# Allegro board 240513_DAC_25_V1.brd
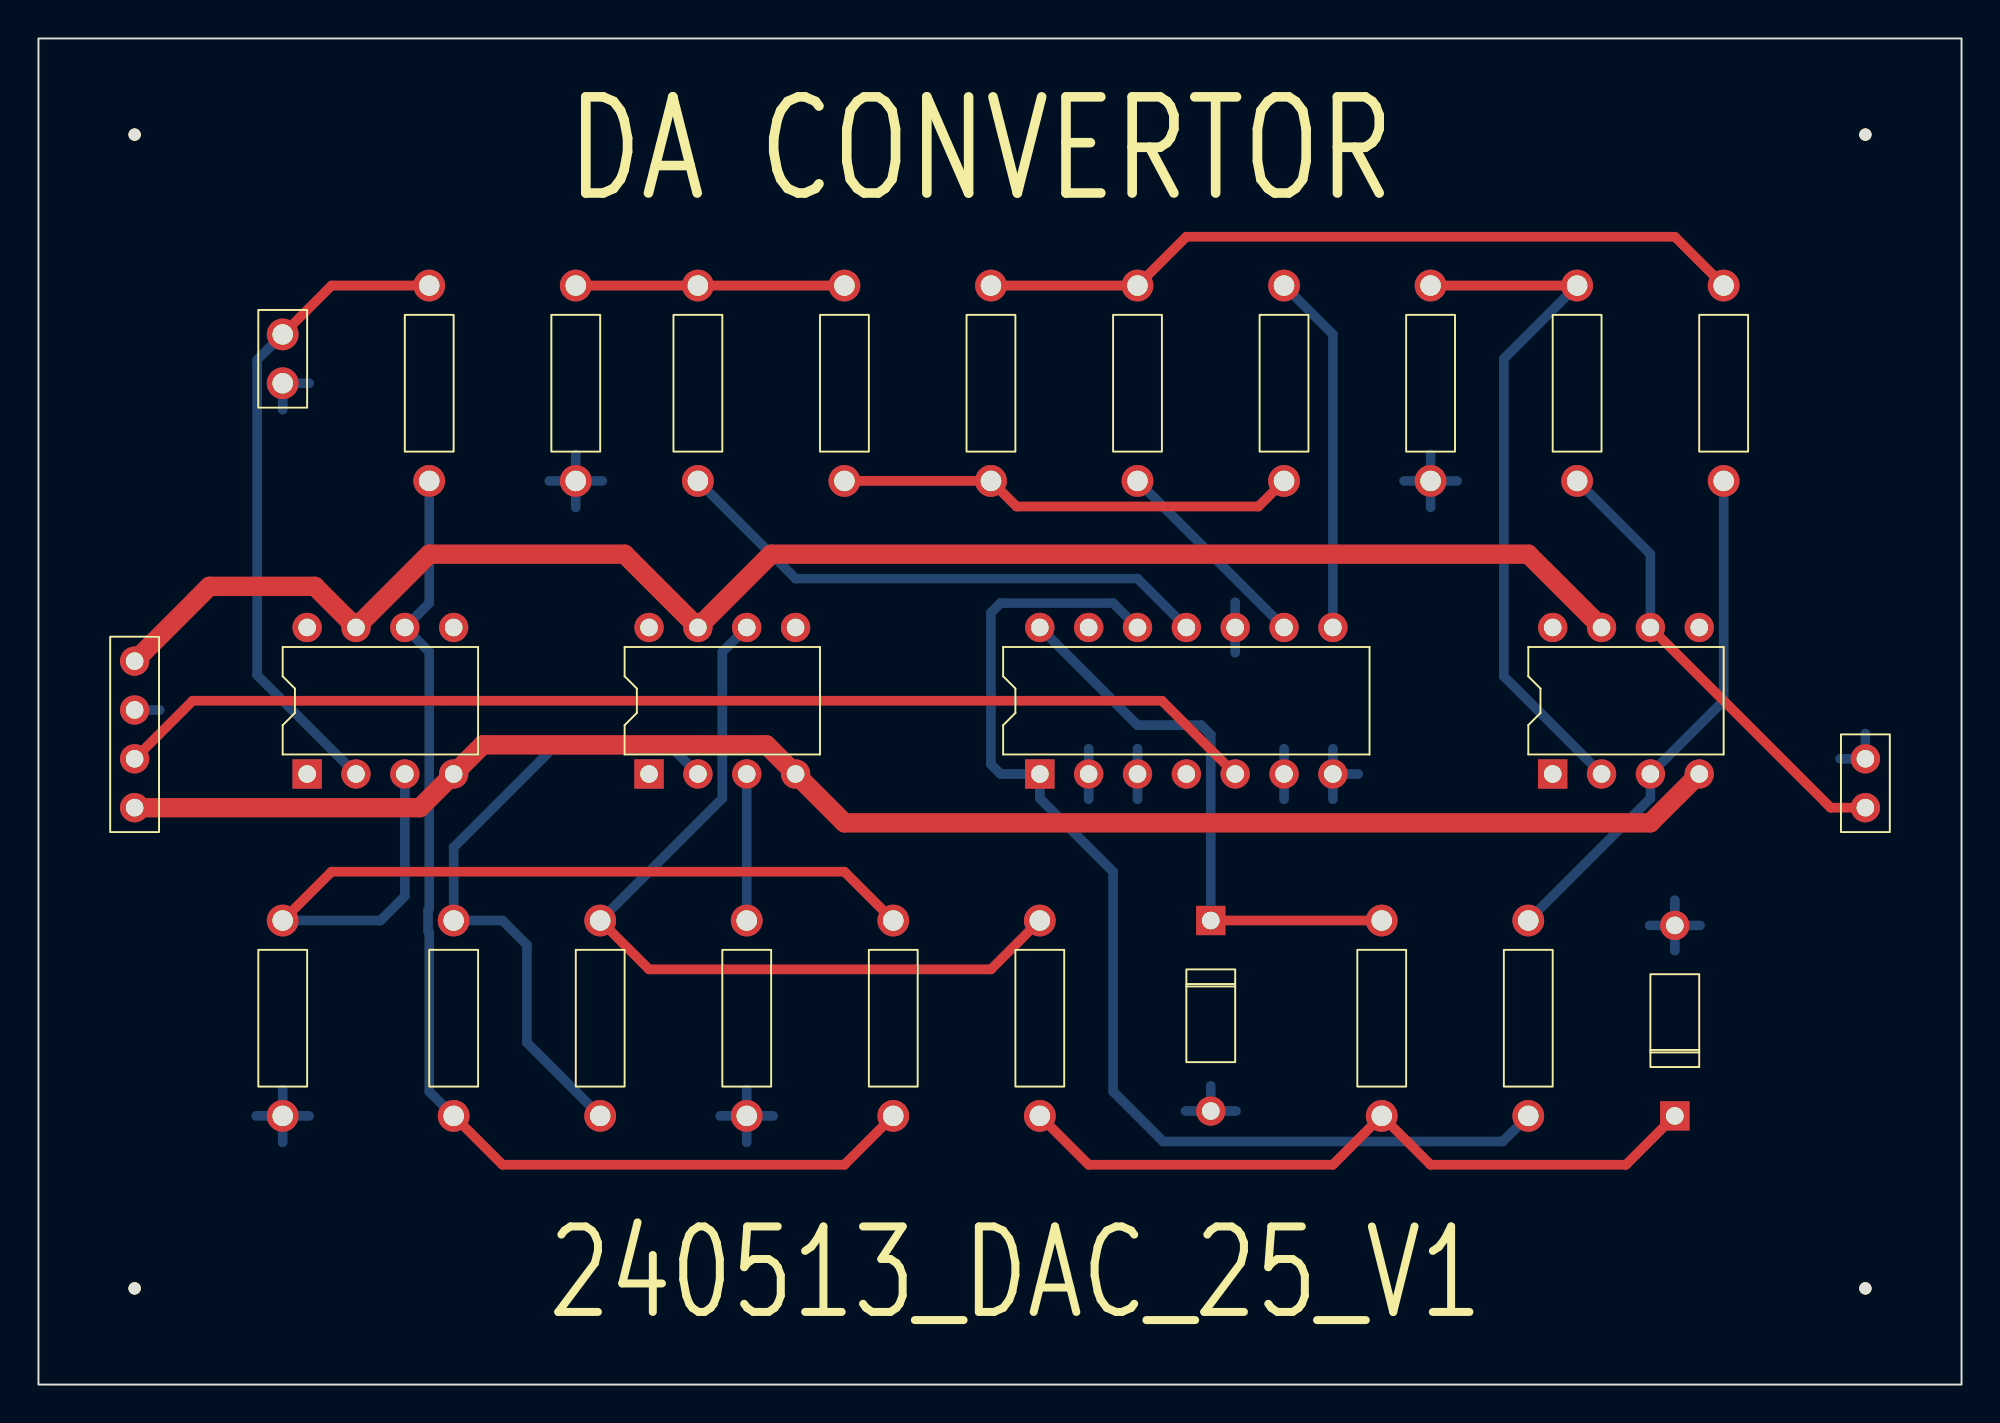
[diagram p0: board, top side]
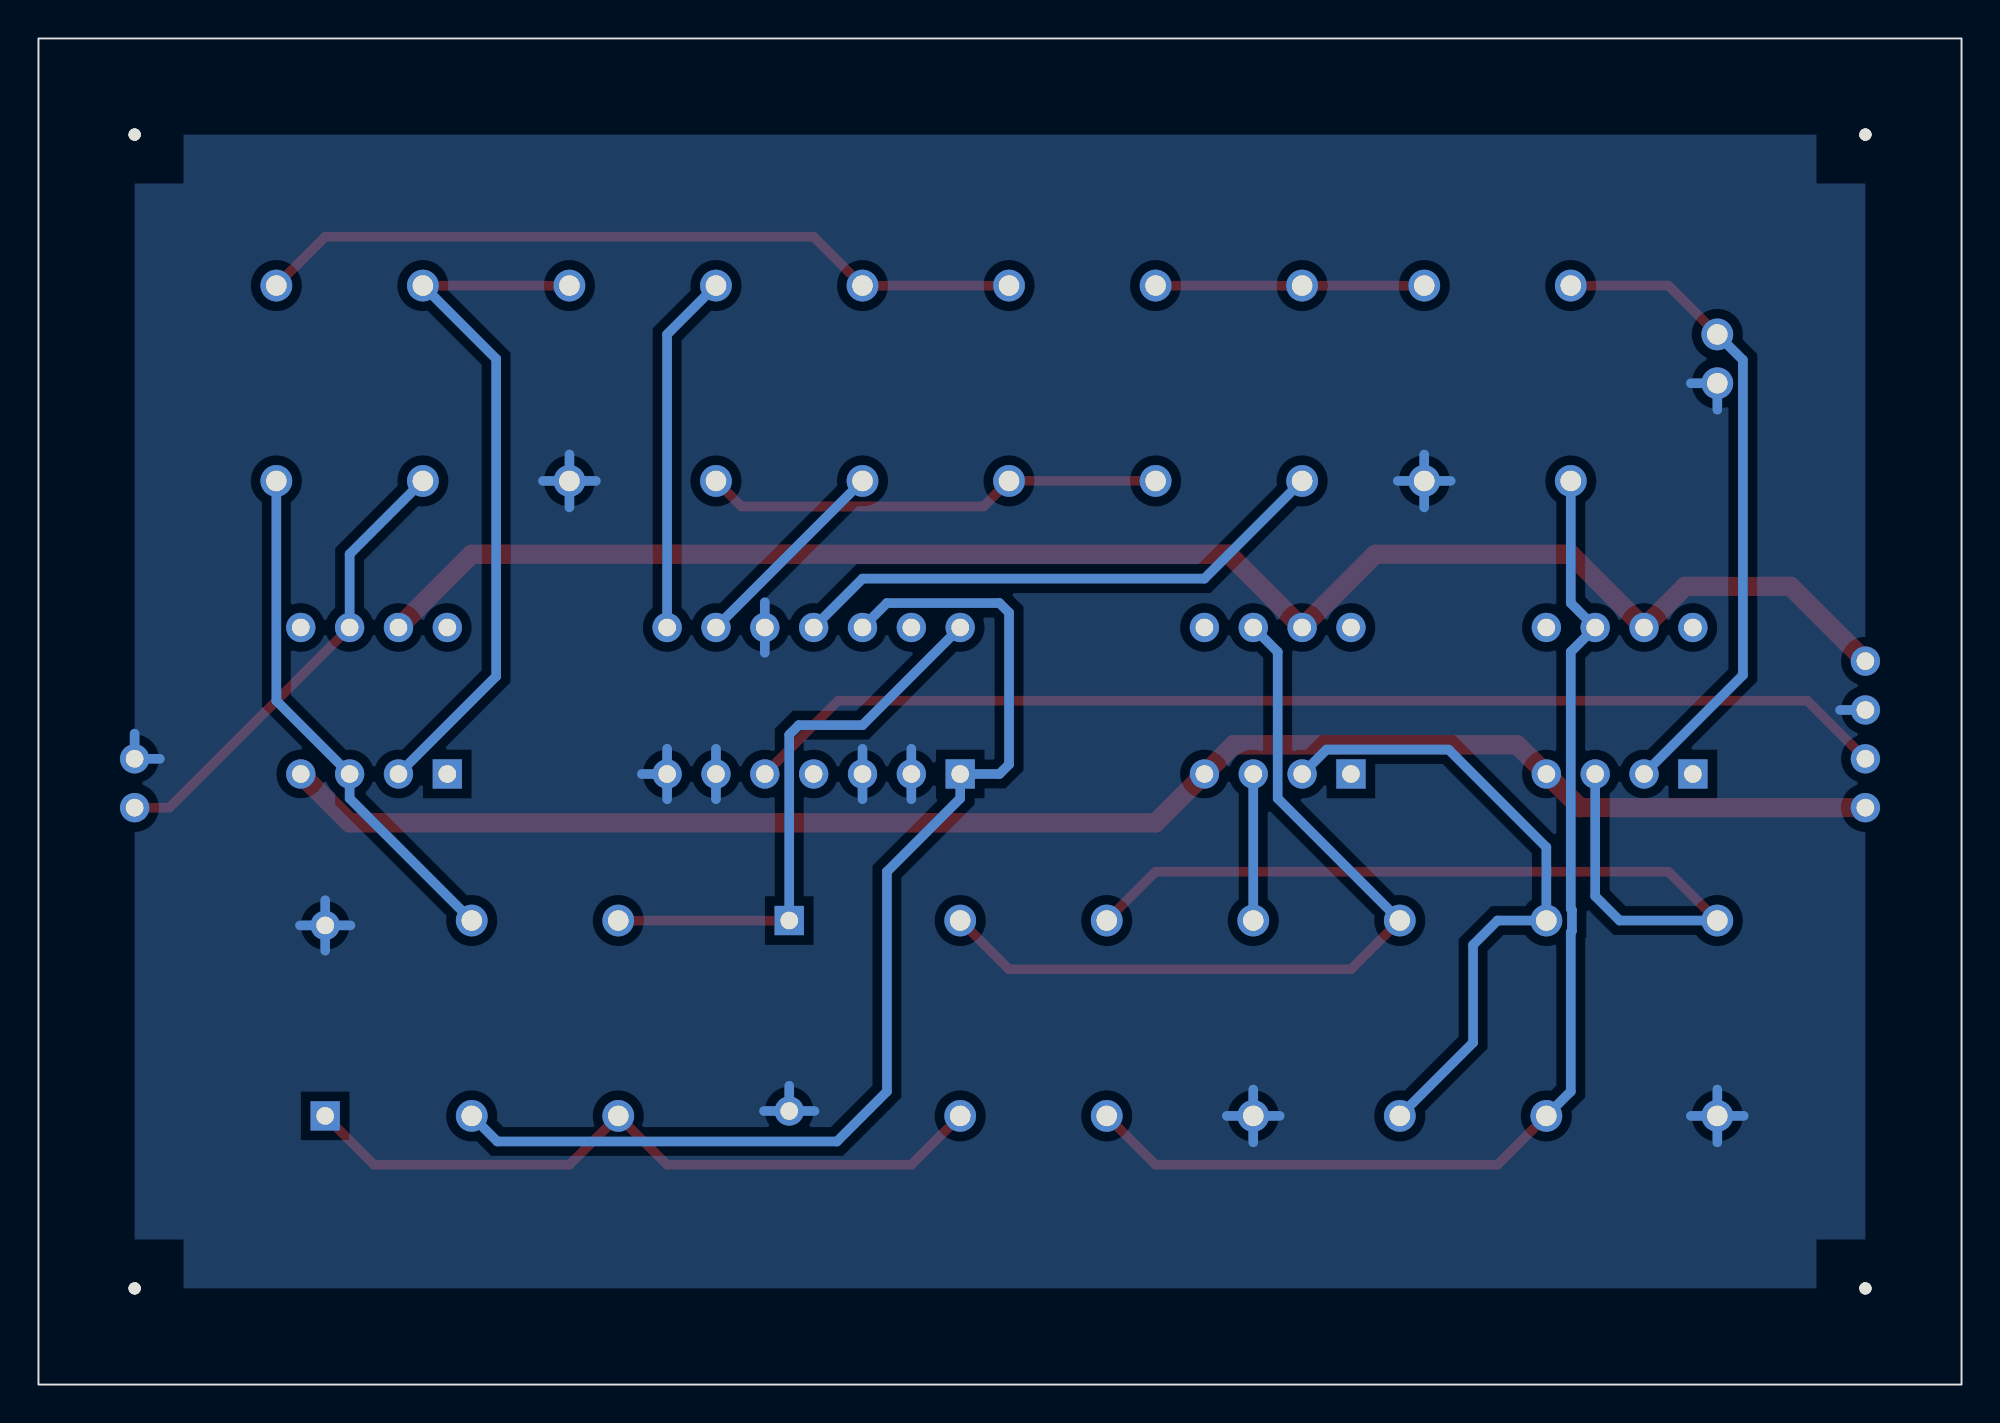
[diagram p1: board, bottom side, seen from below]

Outline 100 x 70 mm; copper layers: TOP, BOTTOM. Coordinates in mm from the lower left corner of the outline.
Outline path: rectangle 0,0 100,70

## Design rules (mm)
nets with their own width: min track width 1; nets +12V -12V GND

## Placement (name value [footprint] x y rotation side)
C1  0.1uF  [CAPCK05]  12.7 54.61 180 top
D1  1N4148  [DO41]  85.09 13.97 0 top
D2  RD5A  [DO41]  60.96 24.13 180 top
J1  CON2  [JUMPER2]  95 30 90 top
J2  CON4  [JUMPER4]  5 30 90 top
NOREF  -  []  5 30 90 top
NOREF#2  -  [unnamed#2]  95 5 0 top
NOREF#3  -  [unnamed#2]  95 65 0 top
NOREF#4  -  []  0 70 0 top
NOREF#5  -  []  5 65 0 top
NOREF#6  -  []  0 70 0 top
NOREF#7  -  [unnamed#2]  5 5 0 top
NOREF#8  -  []  5 65 90 top
NOREF#9  -  []  5 5 90 top
NOREF#10  -  []  100 0 90 top
NOREF#11  -  []  100 0 90 top
NOREF#12  -  []  95 5 90 top
NOREF#13  -  [unnamed#2]  5 65 0 top
R1  10K  [RES400]  20.32 57.15 180 top
R2  5.1K  [RES400]  29.21 13.97 0 top
R3  10K  [RES400]  21.59 13.97 0 top
R4  1K  [RES400]  52.07 24.13 180 top
R5  1K  [RES400]  69.85 13.97 0 top
R6  6.8K  [RES400]  44.45 13.97 0 top
R7  10K  [RES400]  36.83 13.97 0 top
R8  1K  [RES400]  12.7 24.13 180 top
R9  22L  [RES400]  77.47 13.97 0 top
R10  10K  [RES400]  87.63 57.15 180 top
R11  22K  [RES400]  80.01 57.15 180 top
R12  22K  [RES400]  57.15 57.15 180 top
R13  10K  [RES400]  49.53 57.15 180 top
R14  22K  [RES400]  64.77 57.15 180 top
R15  10K  [RES400]  41.91 57.15 180 top
R16  10K  [RES400]  72.39 57.15 180 top
R17  22K  [RES400]  34.29 46.99 0 top
R18  10K  [RES400]  27.94 46.99 0 top
U1  LM741  [DIP8_3]  13.97 31.75 90 top
U2  LM741  [DIP8_3]  31.75 31.75 90 top
U3  74LS90  [DIP14_3]  52.07 31.75 90 top
U4  LM741  [DIP8_3]  78.74 31.75 90 top

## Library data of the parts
C1 = CAP NP: Tolerance: ***; User Part Number: ***
D1 = DIODE
D2 = DIODE ZENER
J1 = CON2: User Part Number: ***
J2 = CON4: User Part Number: ***
R1-R18 = R: Tolerance: ***; User Part Number: ***
U1 = LM741_1: Tolerance: ***; User Part Number: ***
U2 U4 = LM741_2: Tolerance: ***; User Part Number: ***
U3 = 74LS90_1: Tolerance: ***; User Part Number: ***

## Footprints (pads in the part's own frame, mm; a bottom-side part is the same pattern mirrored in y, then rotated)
CAPCK05
  round 1.651 hole 1.067: 1(0,0) 2(0,2.54)
DIP8_3
  rect 1.524x1.524 hole 0.914: 1(0,0)
  round 1.524 hole 0.914: 2(0,-2.54) 3(0,-5.08) 4(0,-7.62) 5(7.62,-7.62) 6(7.62,-5.08) 7(7.62,-2.54) 8(7.62,0)
DIP14_3
  rect 1.524x1.524 hole 0.914: 1(0,0)
  round 1.524 hole 0.914: 2(0,-2.54) 3(0,-5.08) 4(0,-7.62) 5(0,-10.16) 6(0,-12.7) 7(0,-15.24) 8(7.62,-15.24) 9(7.62,-12.7) 10(7.62,-10.16) 11(7.62,-7.62) 12(7.62,-5.08) 13(7.62,-2.54) 14(7.62,0)
DO41
  rect 1.524x1.524 hole 0.914: 1(0,0)
  round 1.524 hole 0.914: 2(0,9.906)
JUMPER2
  round 1.524 hole 0.914: 1(0,0) 2(2.54,0)
JUMPER4
  round 1.524 hole 0.914: 1(0,0) 2(2.54,0) 3(5.08,0) 4(7.62,0)
RES400
  round 1.651 hole 1.067: 1(0,0) 2(0,10.16)
unnamed#2
  round 0.635 hole 3 unplated: (0,0)

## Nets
+12V: J2.1 U1.4(V-) U2.4(V-) U4.4(V-)
-12V: J2.4 U1.7(V+) U2.7(V+) U4.7(V+)
GND: C1.2 D1.2(A) D2.2(ANODE) J1.2 J2.3 R7.1 R8.2 R16.2 R18.1 U3.2(R01) U3.3(R02) U3.6(R91) U3.7(R92) U3.10
VCC: J2.2 U3.5
DA_SG: R9.2 R10.2 U4.3(+IN)
OUT: J1.1 R11.2 U4.6(OUT)
QA: R9.1 U3.1(B) U3.12(QA)
QB: R12.2 U3.9(QB)
QC: R14.1 U3.8(QC)
QD: R17.1 U3.11(QD)
N01760: R1.2 R3.1 R6.1 U1.6(OUT)
N01790: C1.1 R1.1 U1.2(-IN)
N01808: R6.2 R8.1 U1.3(+IN)
N01860: R2.1 R3.2 U2.2(-IN)
N01877: R2.2 R4.1 U2.6(OUT)
N01881: D1.1(K) R4.2 R5.1
N01913: D2.1(CATHODE) R5.2 U3.14(A)
N02059: R11.1 R16.1 U4.2(-IN)
N02108: R7.2 U2.3(+IN)
N02187: R10.1 R12.1 R13.1
N02201: R13.2 R14.2 R15.2
N02215: R15.1 R17.2 R18.2

Pads without a net: U1 1 5 8; U2 1 5 8; U3 4 13; U4 1 5 8

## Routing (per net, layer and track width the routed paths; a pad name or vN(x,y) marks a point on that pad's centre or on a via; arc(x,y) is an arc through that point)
+12V: length 85.4
  TOP w1: J2.1 19.84,30 U1.4 23.11,33.27 37.85,33.27 U2.4 41.91,29.21 83.82,29.21 U4.4
-12V: length 85.1
  TOP w1: U4.7 77.47,43.18 38.1,43.18 U2.7 30.48,43.18 20.32,43.18 U1.7 14.37,41.51 8.89,41.51 J2.4
GND: length 52.4
  BOTTOM w0.5: 27.94,45.61 R18.1 ; R18.1 29.32,46.99 ; R18.1 27.94,48.37 ; R18.1 26.56,46.99 ; 12.7,50.69 C1.2 14.08,52.07 ; 64.77,33.06 U3.6 64.77,30.44 ; R16.2 72.39,48.37 ; R16.2 73.77,46.99 ; R16.2 71.01,46.99 ; R16.2 72.39,45.61 ; D2.2 62.27,14.22 ; D2.2 59.65,14.22 ; D2.2 60.96,15.54 ; U3.7 67.31,33.06 ; U3.7 68.62,31.75 ; U3.7 67.31,30.44 ; R8.2 12.7,15.35 ; R8.2 11.32,13.97 ; R8.2 14.08,13.97 ; R8.2 12.7,12.59 ; D1.2 85.09,25.19 ; D1.2 85.09,22.56 ; D1.2 86.4,23.88 ; D1.2 83.78,23.88 ; 62.23,40.68 U3.10 62.23,38.06 ; 54.61,33.06 U3.2 54.61,30.44 ; 36.83,12.59 R7.1 ; R7.1 35.45,13.97 ; R7.1 38.21,13.97 ; R7.1 36.83,15.35 ; 57.15,33.06 U3.3 57.15,30.44 ; J2.3 6.31,35.08 ; 93.69,32.54 J1.2 95,33.85
VCC: length 60.1
  TOP w0.5: J2.2 8.02,35.56 58.42,35.56 U3.5
DA_SG: length 27.1
  BOTTOM w0.5: R9.2 83.82,30.48 U4.3 87.63,35.56 R10.2
OUT: length 24.3
  TOP w0.5: U4.6 93.19,30 J1.1
  BOTTOM w0.5: U4.6 83.82,43.18 R11.2
QA: length 60.3
  BOTTOM w0.5: U3.12 55.88,40.64 50.03,40.64 49.53,40.14 49.53,32.25 50.03,31.75 U3.1 52.07,30.48 55.88,26.67 55.88,15.24 58.48,12.64 76.14,12.64 R9.1
QB: length 10.8
  BOTTOM w0.5: R12.2 U3.9
QC: length 18.8
  BOTTOM w0.5: U3.8 67.31,54.61 R14.1
QD: length 28.6
  BOTTOM w0.5: U3.11 57.15,41.91 39.37,41.91 R17.1
N01760: length 59.6
  TOP w0.5: R3.1 24.13,11.43 41.91,11.43 R6.1
  BOTTOM w0.5: R1.2 20.32,40.64 U1.6 20.32,38.1 20.32,24.74 20.26,24.68 20.26,23.58 20.32,23.52 20.32,15.24 R3.1
N01790: length 34.2
  TOP w0.5: C1.1 15.24,57.15 R1.1
  BOTTOM w0.5: U1.2 11.37,36.89 11.37,53.28 C1.1
N01808: length 47.1
  TOP w0.5: R8.1 15.24,26.67 41.91,26.67 R6.2
  BOTTOM w0.5: R8.1 17.78,24.13 19.05,25.4 U1.3
N01860: length 33.9
  BOTTOM w0.5: U2.2 33.02,33.02 26.67,33.02 21.59,27.94 R3.2 24.13,24.13 25.4,22.86 25.4,17.78 R2.1
N01877: length 43.4
  TOP w0.5: R2.2 31.75,21.59 49.53,21.59 R4.1
  BOTTOM w0.5: R2.2 35.56,30.48 35.56,38.1 U2.6
N01881: length 37.2
  TOP w0.5: R4.2 54.61,11.43 67.31,11.43 R5.1 72.39,11.43 82.55,11.43 D1.1
N01913: length 29.8
  TOP w0.5: R5.2 D2.1
  BOTTOM w0.5: D2.1 60.96,33.79 60.46,34.29 57.15,34.29 U3.14
N02059: length 36.7
  TOP w0.5: R16.1 R11.1
  BOTTOM w0.5: U4.2 76.2,36.83 76.2,53.34 R11.1
N02108: length 7.6
  BOTTOM w0.5: U2.3 R7.2
N02187: length 40.2
  TOP w0.5: R13.1 R12.1 59.69,59.69 85.09,59.69 R10.1
N02201: length 24
  TOP w0.5: R15.2 R13.2 50.86,45.66 63.44,45.66 R14.2
N02215: length 14
  TOP w0.5: R18.2 R17.2 R15.1

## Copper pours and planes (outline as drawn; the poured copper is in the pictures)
GND on BOTTOM: 5,5 5,65 95,65 95,5

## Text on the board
Ref Des/Silkscreen Top: 240513_DAC_25_V1 | DA CONVERTOR
COMPVAL_TYPE_TOP: FIGURE | SIZE | 0.3302 | 0.9144 | 1.0668 | 3.0 | DRILL CHART: TOP to BOTTOM | ALL UNITS ARE IN MILLIMETERS | PLATED | NON-PLATED | QTY | 7 | 48 | 38 | 4
